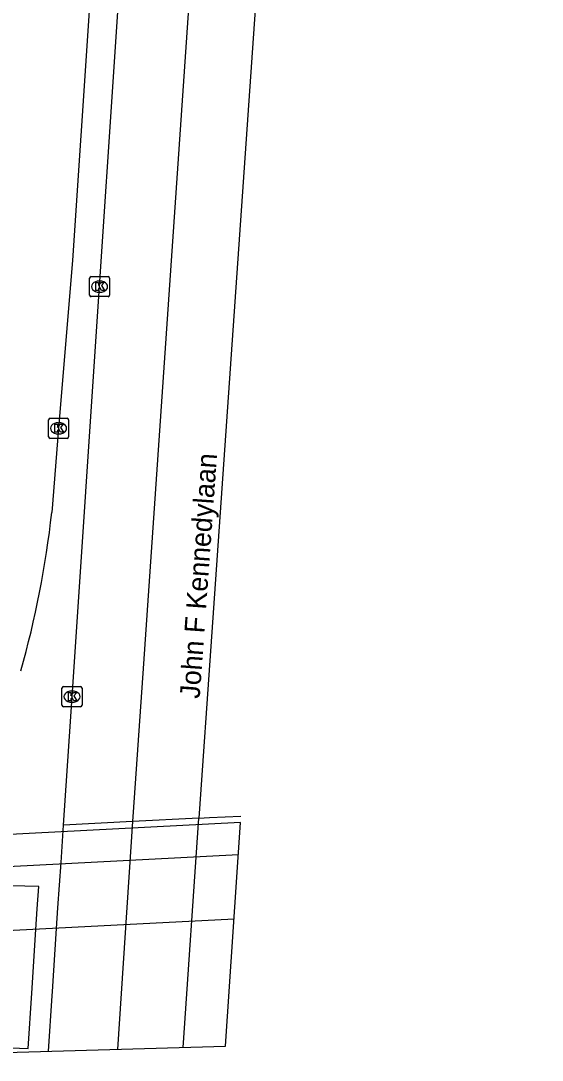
# Model space of a CAD drawing. Extents: x 161084 to 161928, y 385355 to 386522.
# Drawn here: x 161838.2 to 161864.2, y 385382.7 to 385434.6 of the extents above; entities that cross this region are included whole.
import ezdxf

# ---------------------------------------------------------------- set-up
doc = ezdxf.new("R2010")
doc.units = 0
for name, color, linetype in [('IMGEO_Dek', 7, 'Continuous'), ('IMGEO_Fietspad_gesloten', 7, 'Continuous'), ('IMGEO_Kolk', 7, 'Continuous'), ('IMGEO_Openbare_ruimte_label', 7, 'Continuous'), ('IMGEO_Pijler', 7, 'Continuous'), ('IMGEO_Rijbaan_lokaal_gesloten', 7, 'Continuous'), ('IMGEO_Rijbaan_lokaal_open', 7, 'Continuous'), ('IMGEO_Rijbaan_regionaal_gesloten', 7, 'Continuous')]:
    doc.layers.add(name, color=color, linetype=linetype)

msp = doc.modelspace()

# ---------------------------------------------------------------- linework, layer by layer
at = {"layer": 'IMGEO_Dek'}
msp.add_lwpolyline([(161824.116, 385382.664), (161848.414, 385383.364), (161849.156, 385394.524), (161824.831, 385393.274), (161824.722, 385391.662), (161824.508, 385388.475)], close=True, dxfattribs=at)
at = {"layer": 'IMGEO_Fietspad_gesloten'}
msp.add_lwpolyline([(161824.722, 385391.662), (161849.05, 385392.931)], dxfattribs=at)
at = {"layer": 'IMGEO_Kolk'}
for p, q in [((161841.617, 385420.857), (161841.617, 385421.709)), ((161841.692, 385421.783), (161842.544, 385421.783)), ((161842.105, 385421.563), (161842.13, 385421.563)), ((161842.618, 385421.709), (161842.618, 385420.857)), ((161842.128, 385421.003), (161842.103, 385421.003)), ((161842.544, 385420.783), (161841.692, 385420.783)), ((161839.569, 385413.784), (161839.569, 385414.636)), ((161839.644, 385414.71), (161840.496, 385414.71)), ((161840.57, 385414.636), (161840.57, 385413.784)), ((161840.057, 385414.49), (161840.082, 385414.49)), ((161840.496, 385413.71), (161839.644, 385413.71)), ((161840.08, 385413.93), (161840.055, 385413.93)), ((161840.24, 385400.387), (161840.24, 385401.239)), ((161840.315, 385401.313), (161841.167, 385401.313)), ((161841.241, 385401.239), (161841.241, 385400.387)), ((161840.728, 385401.093), (161840.753, 385401.093)), ((161841.167, 385400.313), (161840.315, 385400.313)), ((161840.751, 385400.533), (161840.726, 385400.533))]:
    msp.add_line(p, q, dxfattribs=at)
for points in [[(161841.617, 385420.857), (161841.617, 385421.709)], [(161841.692, 385421.783), (161842.544, 385421.783)], [(161841.938, 385421.483), (161842.061, 385421.483), (161842.061, 385421.332), (161842.191, 385421.483), (161842.355, 385421.483), (161842.209, 385421.332), (161842.362, 385421.083), (161842.21, 385421.083), (161842.125, 385421.247), (161842.061, 385421.18), (161842.061, 385421.083), (161841.938, 385421.083), (161841.938, 385421.483)], [(161842.618, 385421.709), (161842.618, 385420.857)], [(161842.544, 385420.783), (161841.692, 385420.783)], [(161839.569, 385413.784), (161839.569, 385414.636)], [(161839.644, 385414.71), (161840.496, 385414.71)], [(161840.57, 385414.636), (161840.57, 385413.784)], [(161839.89, 385414.41), (161840.013, 385414.41), (161840.013, 385414.259), (161840.143, 385414.41), (161840.307, 385414.41), (161840.161, 385414.259), (161840.314, 385414.01), (161840.162, 385414.01), (161840.077, 385414.174), (161840.013, 385414.107), (161840.013, 385414.01), (161839.89, 385414.01), (161839.89, 385414.41)], [(161840.496, 385413.71), (161839.644, 385413.71)], [(161840.24, 385400.387), (161840.24, 385401.239)], [(161840.315, 385401.313), (161841.167, 385401.313)], [(161841.241, 385401.239), (161841.241, 385400.387)], [(161840.561, 385401.013), (161840.684, 385401.013), (161840.684, 385400.862), (161840.814, 385401.013), (161840.978, 385401.013), (161840.832, 385400.862), (161840.985, 385400.613), (161840.833, 385400.613), (161840.748, 385400.777), (161840.684, 385400.71), (161840.684, 385400.613), (161840.561, 385400.613), (161840.561, 385401.013)], [(161841.167, 385400.313), (161840.315, 385400.313)]]:
    msp.add_lwpolyline(points, dxfattribs=at)
for centre, start, end in [((161841.694, 385421.707), 91.552, 178.448), ((161841.694, 385421.707), 91.552, 178.448), ((161842.542, 385421.707), 1.552, 88.448), ((161842.542, 385421.707), 1.552, 88.448), ((161841.694, 385420.859), 181.552, 268.448), ((161841.694, 385420.859), 181.552, 268.448), ((161842.542, 385420.859), 271.552, 358.448), ((161842.542, 385420.859), 271.552, 358.448), ((161839.646, 385414.634), 91.552, 178.448), ((161839.646, 385414.634), 91.552, 178.448), ((161840.494, 385414.634), 1.552, 88.448), ((161840.494, 385414.634), 1.552, 88.448), ((161839.646, 385413.786), 181.552, 268.448), ((161839.646, 385413.786), 181.552, 268.448), ((161840.494, 385413.786), 271.552, 358.448), ((161840.494, 385413.786), 271.552, 358.448), ((161840.317, 385401.237), 91.552, 178.448), ((161840.317, 385401.237), 91.552, 178.448), ((161841.165, 385401.237), 1.552, 88.448), ((161841.165, 385401.237), 1.552, 88.448), ((161840.317, 385400.389), 181.552, 268.448), ((161840.317, 385400.389), 181.552, 268.448), ((161841.165, 385400.389), 271.552, 358.448), ((161841.165, 385400.389), 271.552, 358.448)]:
    msp.add_arc(centre, 0.0765, start, end, dxfattribs=at)
for centre, major_axis, ratio, start_param, end_param in [((161842.104, 385421.283), (-0.387, 0.002), 0.722429, 4.712389, 7.853982), ((161842.129, 385421.283), (-0.39, 0.002), 0.717154, 1.570796, 4.712389), ((161840.056, 385414.21), (-0.387, 0.002), 0.722429, 4.712389, 7.853982), ((161840.081, 385414.21), (-0.39, 0.002), 0.717154, 1.570796, 4.712389), ((161840.727, 385400.813), (-0.387, 0.002), 0.722429, 4.712389, 7.853982), ((161840.752, 385400.813), (-0.39, 0.002), 0.717154, 1.570796, 4.712389)]:
    msp.add_ellipse(centre, major_axis=major_axis, ratio=ratio, start_param=start_param, end_param=end_param, dxfattribs=at)
at = {"layer": 'IMGEO_Pijler'}
msp.add_lwpolyline([(161838.936, 385389.186), (161839.004, 385390.213), (161839.077, 385391.33), (161836.968, 385391.392), (161836.877, 385390.107), (161836.804, 385389.076), (161836.573, 385385.83), (161836.396, 385383.329), (161838.545, 385383.246), (161838.727, 385386.01)], close=True, dxfattribs=at)
at = {"layer": 'IMGEO_Rijbaan_lokaal_gesloten'}
msp.add_lwpolyline([(161824.508, 385388.475), (161848.836, 385389.717)], dxfattribs=at)
at = {"layer": 'IMGEO_Rijbaan_lokaal_open'}
msp.add_lwpolyline([(161841.605, 385435.058), (161840.769, 385422.585), (161840.069, 385414.21), (161839.728, 385410.002)], dxfattribs=at)
msp.add_arc((161792.28, 385415.181), 47.73, 344.0924, 353.7706, dxfattribs=at)
at = {"layer": 'IMGEO_Rijbaan_regionaal_gesloten'}
for points in [[(161860.496, 385647.553), (161856.595, 385582.716), (161851.574, 385508.138), (161844.294, 385402.219), (161843.769, 385394.576)], [(161864.225, 385647.376), (161854.711, 385505.621), (161852.193, 385468.095), (161847.695, 385403.564), (161847.08, 385394.747)], [(161840.315, 385394.398), (161840.742, 385400.813), (161842.12, 385421.284), (161843.55, 385442.735), (161844.924, 385463.175), (161845.309, 385468.395)], [(161839.562, 385383.109), (161839.747, 385385.876), (161839.761, 385386.097), (161839.971, 385389.239), (161840.039, 385390.264), (161840.191, 385392.532), (161840.297, 385394.134), (161840.315, 385394.398)], [(161843.769, 385394.576), (161840.315, 385394.398)], [(161843.769, 385394.576), (161843.005, 385383.208)], [(161847.08, 385394.747), (161843.769, 385394.576)], [(161846.294, 385383.303), (161847.08, 385394.747)], [(161847.08, 385394.747), (161847.608, 385394.774), (161849.178, 385394.855)]]:
    msp.add_lwpolyline(points, dxfattribs=at)

# ---------------------------------------------------------------- texts
at = {"layer": 'IMGEO_Openbare_ruimte_label'}
msp.add_text('John F Kennedylaan', height=1, rotation=85.9266, dxfattribs=at).set_placement((161847.115, 385400.694))

doc.saveas('drawing.dxf')
